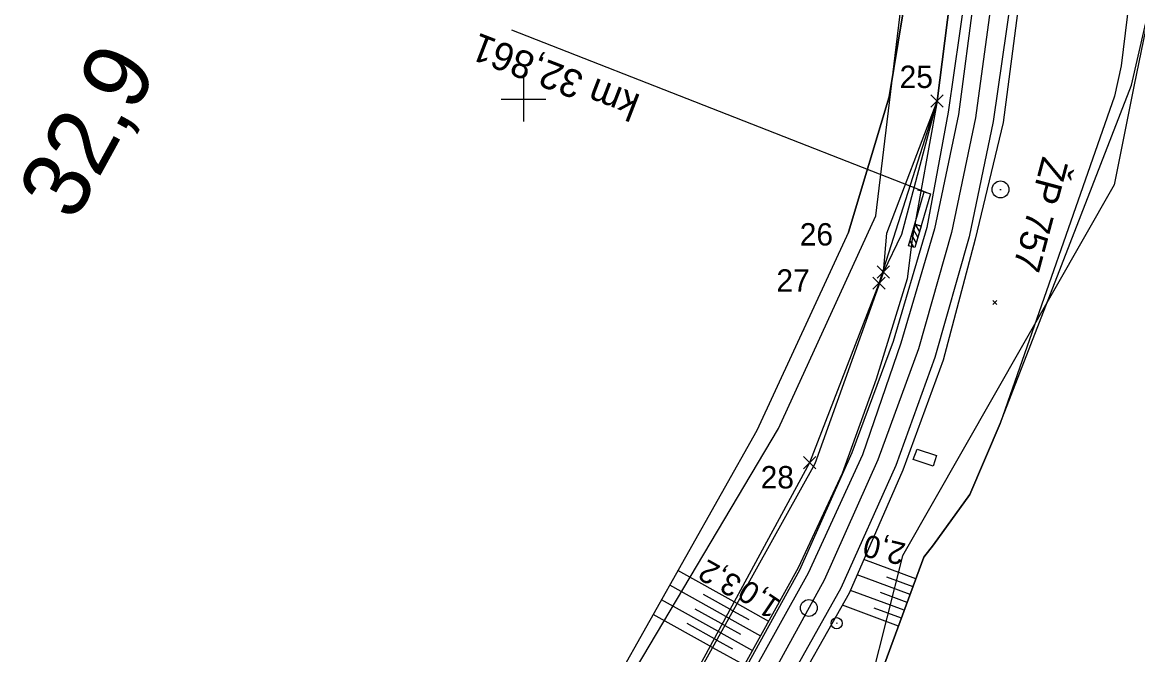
# Model space of a CAD drawing. Extents: x -804166 to -803706, y -1151030 to -1150147.
# Drawn here: x -803944.8 to -803845.1, y -1150649.7 to -1150593.1 of the extents above; entities that cross this region are included whole.
import ezdxf

# ---------------------------------------------------------------- set-up
doc = ezdxf.new("R2010")
doc.units = 0
for name, color, linetype in [('0381KM032-037P - Vrstva 1', 7, 'Continuous'), ('0381KM032-037P - Vrstva 17', 7, 'Continuous'), ('0381KM032-037P - Vrstva 4', 7, 'Continuous'), ('0381KM032-037P - Vrstva 48', 7, 'Continuous'), ('0381KM032-037P - Vrstva 49', 7, 'Continuous'), ('0381KM032-037P - Vrstva 50', 7, 'Continuous'), ('0381KM032-037P - Vrstva 51', 7, 'Continuous'), ('0381KM032-037P - Vrstva 6', 7, 'Continuous'), ('0381KM032-037P - Vrstva 7', 7, 'Continuous'), ('Default', 7, 'Continuous'), ('hran DP - hran DP', 7, 'Continuous'), ('krizky_1000 - Vrstva 1', 7, 'Continuous'), ('PSR_C2_2_Lomove_body_Vimperk - Vrstva 60', 7, 'Continuous'), ('PSR_C2_2_trasa_Vimperk - Kabelová trasa', 7, 'Continuous'), ('vyt_sit - stávající', 7, 'Continuous')]:
    doc.layers.add(name, color=color, linetype=linetype)

msp = doc.modelspace()

# ---------------------------------------------------------------- linework, layer by layer
at = {"layer": '0381KM032-037P - Vrstva 1'}
msp.add_lwpolyline([(-803862.645, -1150536.71), (-803860.057, -1150547.81), (-803858.364, -1150558.718), (-803857.51, -1150569.546), (-803857.425, -1150579.975), (-803858.096, -1150590.725), (-803859.58, -1150601.687), (-803861.73, -1150611.946), (-803864.691, -1150622.329), (-803868.306, -1150632.261), (-803873.118, -1150643.006), (-803878.784, -1150653.323), (-803884.455, -1150662.043), (-803890.68, -1150670.289), (-803894.474, -1150674.768)], dxfattribs=at)
at = {"layer": '0381KM032-037P - Vrstva 17'}
msp.add_lwpolyline([(-803867.911, -1150651.01), (-803864.194, -1150640.965), (-803863.34, -1150639.848), (-803860.107, -1150635.351), (-803857.384, -1150629.008), (-803845.634, -1150598.77), (-803839.769, -1150573.178), (-803837.289, -1150572.72)], dxfattribs=at)
at = {"layer": '0381KM032-037P - Vrstva 4'}
for points in [[(-803872.779, -1150506.875), (-803867.872, -1150516.171), (-803864.004, -1150525.679), (-803860.599, -1150536.286), (-803857.956, -1150547.888), (-803856.113, -1150558.65), (-803855.009, -1150569.422), (-803855.013, -1150580.14), (-803855.681, -1150591.137), (-803857.109, -1150602.102)], [(-803872.779, -1150506.875), (-803868.424, -1150516.34), (-803864.491, -1150525.922), (-803861.191, -1150536.397), (-803858.415, -1150547.949), (-803856.721, -1150558.765), (-803855.706, -1150569.464), (-803855.706, -1150580.041), (-803856.439, -1150591.045), (-803858.016, -1150602.009)], [(-803875.392, -1150508.511), (-803871.454, -1150517.68), (-803867.834, -1150527.236), (-803864.663, -1150537.291), (-803862.152, -1150548.382), (-803860.595, -1150558.999), (-803859.922, -1150569.628), (-803859.947, -1150579.801), (-803860.5, -1150590.58), (-803862.041, -1150601.171)], [(-803859.085, -1150579.867), (-803859.701, -1150590.693), (-803861.107, -1150601.386)], [(-803862.041, -1150601.171), (-803863.934, -1150611.478), (-803866.955, -1150621.666), (-803870.636, -1150631.623), (-803875.322, -1150642.112), (-803880.813, -1150652.073), (-803886.36, -1150660.761), (-803891.5, -1150667.581), (-803892.695, -1150669.921)], [(-803861.107, -1150601.386), (-803863.249, -1150611.592), (-803866.278, -1150621.841), (-803869.683, -1150631.826), (-803874.548, -1150642.393), (-803880.159, -1150652.477), (-803885.847, -1150661.208), (-803892.695, -1150669.921)], [(-803858.016, -1150602.009), (-803860.157, -1150612.315), (-803863.229, -1150623.106), (-803866.722, -1150632.775), (-803871.621, -1150643.742), (-803877.472, -1150654.13), (-803883.137, -1150662.978), (-803889.477, -1150671.458), (-803892.178, -1150675.246)], [(-803857.109, -1150602.102), (-803859.611, -1150612.518), (-803862.49, -1150623.34), (-803866.1, -1150633.182), (-803870.873, -1150644.181), (-803876.806, -1150654.687), (-803882.51, -1150663.405), (-803892.178, -1150675.246)]]:
    msp.add_lwpolyline(points, dxfattribs=at)
at = {"layer": '0381KM032-037P - Vrstva 48'}
for p, q in [((-803864.911, -1150642.902), (-803869.57, -1150641.178)), ((-803880.906, -1150645.106), (-803886.195, -1150642.162)), ((-803865.431, -1150644.309), (-803870.168, -1150642.556)), ((-803865.171, -1150643.606), (-803867.52, -1150642.736)), ((-803881.635, -1150646.417), (-803886.93, -1150643.47)), ((-803865.952, -1150645.716), (-803870.766, -1150643.934)), ((-803882.365, -1150647.727), (-803887.665, -1150644.777)), ((-803881.27, -1150645.761), (-803883.916, -1150644.289)), ((-803865.692, -1150645.012), (-803868.079, -1150644.129)), ((-803882, -1150647.072), (-803884.649, -1150645.598)), ((-803881.27, -1150645.76), (-803879.86, -1150646.545)), ((-803880.905, -1150645.105), (-803878.088, -1150646.673)), ((-803866.473, -1150647.123), (-803871.486, -1150645.267)), ((-803866.212, -1150646.419), (-803868.663, -1150645.512)), ((-803883.094, -1150649.038), (-803888.401, -1150646.085)), ((-803882.729, -1150648.383), (-803885.381, -1150646.907)), ((-803881.635, -1150646.416), (-803878.814, -1150647.986)), ((-803882.364, -1150647.726), (-803879.539, -1150649.299)), ((-803881.999, -1150647.071), (-803880.588, -1150647.857)), ((-803882.729, -1150648.382), (-803881.315, -1150649.168)), ((-803883.093, -1150649.037), (-803880.278, -1150650.604))]:
    msp.add_line(p, q, dxfattribs=at)
at = {"layer": '0381KM032-037P - Vrstva 49'}
for p, q in [((-803870.937, -1150611.902), (-803879.144, -1150629.624)), ((-803858.047, -1150618.024), (-803857.693, -1150618.376)), ((-803857.694, -1150618.023), (-803858.046, -1150618.377))]:
    msp.add_line(p, q, dxfattribs=at)
for points in [[(-803888.13, -1150522.065), (-803877.502, -1150535.708), (-803870.854, -1150543.675), (-803863.849, -1150556.524), (-803862.399, -1150570.315), (-803861.636, -1150589.369), (-803863.02, -1150600.178)], [(-803888.331, -1150532.703), (-803880.592, -1150540.151), (-803872.905, -1150546.743), (-803867.412, -1150556.856), (-803866.176, -1150570.896), (-803865.67, -1150589.811), (-803867.321, -1150599.808), (-803870.937, -1150611.902)], [(-803838.825, -1150566.88), (-803844.043, -1150574.496), (-803844.762, -1150582.145), (-803846.556, -1150597.039), (-803847.173, -1150599.748), (-803857.384, -1150629.008)], [(-803855.009, -1150569.422), (-803855.013, -1150580.14), (-803855.681, -1150591.137), (-803857.109, -1150602.102), (-803859.611, -1150612.518), (-803862.49, -1150623.34), (-803866.1, -1150633.182), (-803870.873, -1150644.181), (-803876.806, -1150654.687), (-803882.51, -1150663.405)], [(-803867.826, -1150615.469), (-803867.512, -1150611.999), (-803863.02, -1150600.178)], [(-803867.826, -1150615.469), (-803866.177, -1150612.082), (-803863.02, -1150600.178)], [(-803863.02, -1150600.178), (-803865.264, -1150612.536), (-803865.684, -1150616.069)], [(-803867.826, -1150615.469), (-803873.958, -1150632.621), (-803887.064, -1150656.172), (-803894.324, -1150662.675), (-803894.538, -1150670.386)], [(-803865.684, -1150616.069), (-803868.473, -1150625.045), (-803871.506, -1150633.468), (-803875.458, -1150641.91), (-803880.036, -1150650.199), (-803884.384, -1150657.469), (-803889.567, -1150664.922), (-803894.538, -1150670.386)], [(-803879.144, -1150629.624), (-803891.889, -1150652.288), (-803898.32, -1150663.448), (-803898.278, -1150667.796), (-803897.353, -1150671.802), (-803897.063, -1150673.395), (-803895.285, -1150678.85), (-803893.718, -1150680.524), (-803892.244, -1150682.081)], [(-803857.384, -1150629.008), (-803860.107, -1150635.351), (-803863.34, -1150639.848), (-803864.194, -1150640.965), (-803867.911, -1150651.01), (-803869.632, -1150654.159), (-803870.889, -1150656.426), (-803877.877, -1150667.643), (-803881.038, -1150676.732), (-803882.094, -1150681.238), (-803882.068, -1150682.623)]]:
    msp.add_lwpolyline(points, dxfattribs=at)
at = {"layer": '0381KM032-037P - Vrstva 50'}
for points in [[(-803870.937, -1150611.902), (-803867.321, -1150599.808), (-803865.67, -1150589.811), (-803866.176, -1150570.896), (-803867.412, -1150556.856), (-803872.905, -1150546.743), (-803880.592, -1150540.151), (-803888.331, -1150532.703), (-803894.19, -1150526.416), (-803900.653, -1150518.475)], [(-803870.937, -1150611.902), (-803879.144, -1150629.624), (-803891.889, -1150652.288), (-803898.32, -1150663.448), (-803898.278, -1150667.796), (-803897.353, -1150671.802), (-803897.063, -1150673.395)]]:
    msp.add_lwpolyline(points, dxfattribs=at)
at = {"layer": '0381KM032-037P - Vrstva 51'}
msp.add_lwpolyline([(-803863.373, -1150632.821), (-803865.148, -1150632.231), (-803864.816, -1150631.297), (-803863.081, -1150631.879), (-803863.373, -1150632.821)], dxfattribs=at)
at = {"layer": '0381KM032-037P - Vrstva 6'}
for p, q in [((-803863.898, -1150608.391), (-803901.037, -1150593.855)), ((-803864.186, -1150608.308), (-803864.763, -1150608.141)), ((-803865.153, -1150611.649), (-803864.743, -1150612.392)), ((-803864.444, -1150611.356), (-803865.02, -1150611.189)), ((-803864.97, -1150611.204), (-803864.596, -1150611.883)), ((-803864.46, -1150611.351), (-803864.448, -1150611.372)), ((-803864.444, -1150611.356), (-803864.444, -1150611.356)), ((-803865.448, -1150612.668), (-803865.133, -1150613.239)), ((-803865.3, -1150612.158), (-803864.891, -1150612.901))]:
    msp.add_line(p, q, dxfattribs=at)
msp.add_lwpolyline([(-803863.61, -1150608.474), (-803865, -1150613.277), (-803865.576, -1150613.111), (-803864.186, -1150608.308), (-803863.61, -1150608.474)], dxfattribs=at)
msp.add_lwpolyline([(-803865.576, -1150613.111), (-803865.02, -1150611.189), (-803864.444, -1150611.356), (-803865, -1150613.277)], close=True, dxfattribs=at)
at = {"layer": '0381KM032-037P - Vrstva 7'}
msp.add_line((-803871.973, -1150646.824), (-803872.021, -1150646.912), dxfattribs=at)
for centre, radius in [((-803874.49, -1150645.505), 0.75), ((-803871.997, -1150646.868), 0.5)]:
    msp.add_circle(centre, radius, dxfattribs=at)
at = {"layer": 'hran DP - hran DP'}
for p, q in [((-803868.49, -1150610.44), (-803863.95, -1150572.75)), ((-803842.82, -1150586.3), (-803845.41, -1150598.72)), ((-803845.41, -1150598.72), (-803847.18, -1150607.67)), ((-803847.18, -1150607.67), (-803866.11, -1150640.84)), ((-803877.2, -1150629.46), (-803868.49, -1150610.44)), ((-803894.67, -1150658.87), (-803877.2, -1150629.46)), ((-803866.11, -1150640.84), (-803869.51, -1150654.24))]:
    msp.add_line(p, q, dxfattribs=at)
at = {"layer": 'krizky_1000 - Vrstva 1'}
for points in [[(-803900, -1150598), (-803900, -1150602)], [(-803902, -1150600), (-803898, -1150600)]]:
    msp.add_lwpolyline(points, dxfattribs=at)
at = {"layer": 'PSR_C2_2_Lomove_body_Vimperk - Vrstva 60'}
for p, q in [((-803863.57, -1150600.728), (-803862.47, -1150599.628)), ((-803862.47, -1150600.728), (-803863.57, -1150599.628)), ((-803868.376, -1150616.019), (-803867.276, -1150614.919)), ((-803867.276, -1150616.019), (-803868.376, -1150614.919)), ((-803868.76, -1150617.013), (-803867.66, -1150615.913)), ((-803867.66, -1150617.013), (-803868.76, -1150615.913)), ((-803874.962, -1150633.051), (-803873.862, -1150631.951)), ((-803873.862, -1150633.051), (-803874.962, -1150631.951))]:
    msp.add_line(p, q, dxfattribs=at)
at = {"layer": 'PSR_C2_2_trasa_Vimperk - Kabelová trasa'}
for points in [[(-803868.21, -1150616.463), (-803863.02, -1150600.178), (-803861.636, -1150589.369), (-803860.999, -1150569.821), (-803861.329, -1150559.178)], [(-803893.852, -1150661.817), (-803887.129, -1150655.981), (-803874.412, -1150632.501), (-803867.826, -1150615.469)]]:
    msp.add_lwpolyline(points, dxfattribs=at)
at = {"layer": 'vyt_sit - stávající'}
msp.add_line((-803857.401, -1150608.078), (-803857.301, -1150608.078), dxfattribs=at)
msp.add_circle((-803857.351, -1150608.078), 0.756, dxfattribs=at)

# ---------------------------------------------------------------- texts
at = {"layer": '0381KM032-037P - Vrstva 48'}
for s, rotation, p in [('2,0', 166.54164, (-803865.72, -1150639.769)), ('3,2', 150.64897, (-803880.336, -1150642.91)), ('1,0', 145.90431, (-803876.829, -1150644.97))]:
    msp.add_text(s, height=2, rotation=rotation, dxfattribs=at).set_placement(p)
at = {"layer": '0381KM032-037P - Vrstva 6'}
msp.add_text('km 32,861', height=2.5, rotation=158.86045, dxfattribs=at).set_placement((-803889.433, -1150599.681))
at = {"layer": '0381KM032-037P - Vrstva 7'}
msp.add_text('32,9', height=6, rotation=61.22482, dxfattribs=at).set_placement((-803940.167, -1150611.093))
at = {"layer": 'Default'}
for s, p in [('25', (-803866.371, -1150599.012)), ('26', (-803875.302, -1150613.096)), ('27', (-803877.388, -1150617.223)), ('28', (-803878.795, -1150634.816))]:
    msp.add_text(s, height=2, dxfattribs=at).set_placement(p)
at = {"layer": 'vyt_sit - stávající'}
msp.add_text('ŽP 757', height=2.4, rotation=255, dxfattribs=at).set_placement((-803853.581, -1150605.05))

doc.saveas('drawing.dxf')
